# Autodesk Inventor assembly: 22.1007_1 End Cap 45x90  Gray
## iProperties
Created: 2012-02
Part Number: 22.1007_1 End Cap 45x90  Gray
Document SubType Name: Assembly
Designer: Administrator
Author: Administrator
